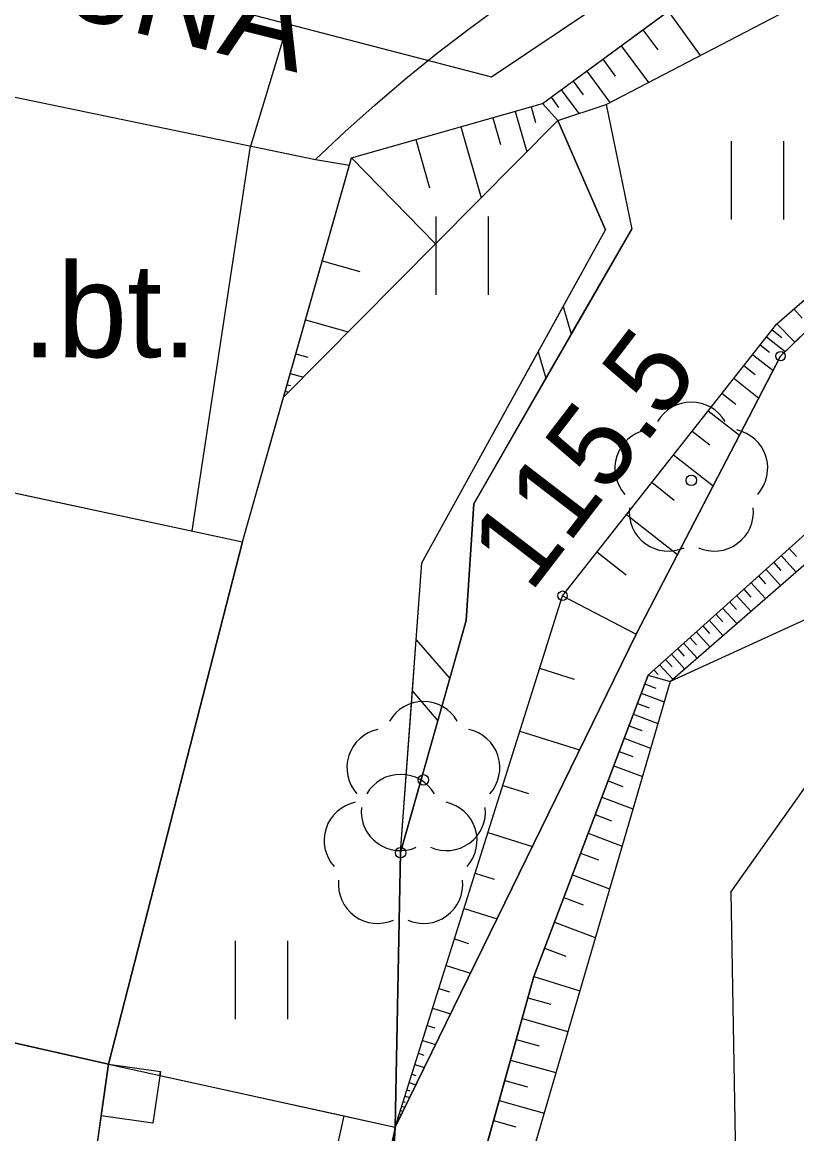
# Model space of a CAD drawing. Extents: x 6434771 to 6436222, y 5663454 to 5664782.
# Drawn here: x 6434919.55 to 6434926.97, y 5664029.23 to 5664039.87 of the extents above; entities that cross this region are included whole.
import ezdxf

# ---------------------------------------------------------------- set-up
doc = ezdxf.new("R2010")
doc.units = 0
for name, color, linetype in [('Warstwa 1', 7, 'Continuous'), ('Warstwa 10', 7, 'Continuous'), ('Warstwa 11', 7, 'Continuous'), ('Warstwa 12', 7, 'Continuous'), ('Warstwa 13', 7, 'Continuous'), ('Warstwa 2', 7, 'Continuous'), ('Warstwa 20', 7, 'Continuous'), ('Warstwa 21', 7, 'Continuous'), ('Warstwa 33', 7, 'Continuous'), ('Warstwa 5', 7, 'Continuous'), ('Warstwa 51', 7, 'Continuous'), ('Warstwa 8', 7, 'Continuous'), ('Warstwa 9', 7, 'Continuous')]:
    doc.layers.add(name, color=color, linetype=linetype)

msp = doc.modelspace()

# ---------------------------------------------------------------- linework, layer by layer
at = {"layer": 'Warstwa 1'}
for q in [(6434931.371, 5664038.648), (6434926.577, 5664017.347)]:
    msp.add_line((6434926.337, 5664031.543), q, dxfattribs=at)
for points in [[(6434917.94, 5664035.694), (6434921.661, 5664034.898), (6434920.38, 5664029.894), (6434916.633, 5664030.739)], [(6434911.812, 5664031.828), (6434920.38, 5664029.894), (6434918.982, 5664020.154), (6434921.832, 5664020.166), (6434921.856, 5664014.645), (6434919.005, 5664014.634), (6434920.397, 5664004.883), (6434911.753, 5664002.928), (6434910.828, 5664006.639), (6434910.117, 5664010.758), (6434909.494, 5664014.626), (6434909.488, 5664017.416), (6434909.44, 5664020.046), (6434910.163, 5664023.638), (6434910.979, 5664028.218)]]:
    msp.add_lwpolyline(points, close=True, dxfattribs=at)
at = {"layer": 'Warstwa 10'}
for p, q in [((6434925.142, 5664039.086), (6434929.479, 5664041.344)), ((6434924.532, 5664039.094), (6434926.338, 5664040.422)), ((6434925.735, 5664039.978), (6434926.044, 5664039.556)), ((6434925.494, 5664039.802), (6434925.636, 5664039.609)), ((6434925.288, 5664039.649), (6434925.547, 5664039.297)), ((6434925.11, 5664039.52), (6434925.23, 5664039.357)), ((6434924.958, 5664039.406), (6434925.179, 5664039.106)), ((6434924.826, 5664039.31), (6434924.924, 5664039.178)), ((6434924.712, 5664039.226), (6434924.88, 5664038.998)), ((6434922.705, 5664038.576), (6434924.532, 5664039.094)), ((6434924.532, 5664039.094), (6434924.68, 5664038.932)), ((6434924.68, 5664038.932), (6434924.532, 5664039.094)), ((6434924.615, 5664039.156), (6434924.688, 5664039.057)), ((6434924.68, 5664038.932), (6434925.142, 5664039.086)), ((6434924.273, 5664039.02), (6434924.383, 5664038.632)), ((6434924.424, 5664039.063), (6434924.467, 5664038.912)), ((6434923.515, 5664037.757), (6434924.68, 5664038.932)), ((6434923.753, 5664038.873), (6434923.946, 5664038.192)), ((6434924.058, 5664038.959), (6434924.13, 5664038.704)), ((6434923.321, 5664038.75), (6434923.453, 5664038.289)), ((6434922.054, 5664036.284), (6434922.705, 5664038.576)), ((6434922.705, 5664038.576), (6434923.509, 5664037.752)), ((6434925.546, 5664033.621), (6434930.763, 5664038.318)), ((6434925.755, 5664033.559), (6434930.9, 5664038.046)), ((6434922.054, 5664036.284), (6434923.515, 5664037.757)), ((6434922.425, 5664037.588), (6434922.785, 5664037.486)), ((6434922.264, 5664037.023), (6434922.673, 5664036.907)), ((6434922.171, 5664036.697), (6434922.286, 5664036.665)), ((6434922.119, 5664036.51), (6434922.244, 5664036.474)), ((6434922.07, 5664036.339), (6434922.101, 5664036.331)), ((6434922.088, 5664036.402), (6434922.121, 5664036.393)), ((6434922.061, 5664036.304), (6434922.066, 5664036.302)), ((6434926.893, 5664034.835), (6434926.965, 5664034.756)), ((6434926.819, 5664034.767), (6434926.96, 5664034.61)), ((6434926.672, 5664034.634), (6434926.811, 5664034.48)), ((6434926.745, 5664034.701), (6434926.815, 5664034.623)), ((6434926.529, 5664034.507), (6434926.668, 5664034.355)), ((6434926.6, 5664034.57), (6434926.669, 5664034.494)), ((6434926.46, 5664034.444), (6434926.528, 5664034.368)), ((6434926.325, 5664034.323), (6434926.392, 5664034.248)), ((6434926.392, 5664034.383), (6434926.527, 5664034.232)), ((6434926.194, 5664034.204), (6434926.26, 5664034.13)), ((6434926.258, 5664034.263), (6434926.393, 5664034.115)), ((6434926.067, 5664034.091), (6434926.132, 5664034.018)), ((6434926.13, 5664034.147), (6434926.261, 5664034)), ((6434925.945, 5664033.98), (6434926.009, 5664033.909)), ((6434926.006, 5664034.035), (6434926.135, 5664033.891)), ((6434925.826, 5664033.874), (6434925.89, 5664033.803)), ((6434925.884, 5664033.926), (6434926.013, 5664033.783)), ((6434925.711, 5664033.77), (6434925.775, 5664033.7)), ((6434925.768, 5664033.821), (6434925.894, 5664033.681)), ((6434925.6, 5664033.67), (6434925.641, 5664033.625)), ((6434925.655, 5664033.72), (6434925.78, 5664033.58)), ((6434925.546, 5664033.621), (6434925.755, 5664033.559)), ((6434925.546, 5664033.621), (6434925.755, 5664033.559))]:
    msp.add_line(p, q, dxfattribs=at)
at = {"layer": 'Warstwa 11'}
msp.add_lwpolyline([(6434966.756, 5664003.6), (6434966.415, 5664007.644), (6434965.276, 5664011.028), (6434962.407, 5664016.883), (6434961.412, 5664023.136), (6434959.23, 5664027.952), (6434956.702, 5664030.613), (6434952.189, 5664033.718), (6434942.648, 5664038.634), (6434938.947, 5664040.259), (6434935.85, 5664038.056), (6434933.246, 5664036.108), (6434929.415, 5664035.234), (6434925.755, 5664033.559), (6434924.242, 5664028.377), (6434923.988, 5664023.91), (6434923.741, 5664023.373), (6434924.496, 5664011.353), (6434925.122, 5664008.575), (6434925.857, 5664004.846)], dxfattribs=at)
for centre in [(6434925.958, 5664035.486), (6434923.393, 5664032.617), (6434923.175, 5664031.92)]:
    msp.add_circle(centre, 0.05, dxfattribs=at)
for centre, start, end in [((6434925.958, 5664035.861), 30.1471, 149.8529), ((6434925.601, 5664035.602), 102.1471, 221.8529), ((6434926.315, 5664035.602), 318.1471, 77.8529), ((6434925.738, 5664035.183), 174.1471, 293.8529), ((6434926.178, 5664035.183), 246.1471, 5.8529), ((6434923.393, 5664032.992), 30.1471, 149.8529), ((6434923.036, 5664032.733), 102.1471, 221.8529), ((6434923.75, 5664032.733), 318.1471, 77.8529), ((6434923.175, 5664032.295), 30.1471, 149.8529), ((6434922.818, 5664032.036), 102.1471, 221.8529), ((6434923.532, 5664032.036), 318.1471, 77.8529), ((6434923.173, 5664032.314), 174.1471, 293.8529), ((6434923.613, 5664032.314), 246.1471, 5.8529), ((6434922.955, 5664031.617), 174.1471, 293.8529), ((6434923.395, 5664031.617), 246.1471, 5.8529)]:
    msp.add_arc(centre, 0.375, start, end, dxfattribs=at)
at = {"layer": 'Warstwa 12'}
for points in [[(6434921.179, 5664035.001), (6434921.736, 5664038.668), (6434924.809, 5664048.81)], [(6434916.87, 5664040.657), (6434919.588, 5664040.514), (6434924.045, 5664039.35), (6434927.322, 5664041.55), (6434931.207, 5664042.783), (6434934.74, 5664042.98), (6434942.258, 5664041.148), (6434950.666, 5664036.716), (6434956.042, 5664033.861), (6434958.491, 5664032.141), (6434963.807, 5664027.637), (6434974.145, 5664019.101)]]:
    msp.add_lwpolyline(points, dxfattribs=at)
at = {"layer": 'Warstwa 13'}
for centre in [(6434926.813, 5664036.676), (6434924.725, 5664034.381)]:
    msp.add_circle(centre, 0.045, dxfattribs=at)
at = {"layer": 'Warstwa 2'}
msp.add_lwpolyline([(6434921.661, 5664034.898), (6434922.705, 5664038.576), (6434924.532, 5664039.094), (6434926.338, 5664040.422), (6434928.301, 5664041.518), (6434930.459, 5664042.152), (6434933.603, 5664042.424), (6434935.842, 5664042.316), (6434938.067, 5664041.859), (6434940.24, 5664041.293), (6434942.361, 5664040.517), (6434946.478, 5664038.627), (6434952.38, 5664035.426), (6434958.066, 5664031.766), (6434964.917, 5664026.013)], dxfattribs=at)
at = {"layer": 'Warstwa 20'}
for p, q in [((6434924.532, 5664039.094), (6434926.338, 5664040.422)), ((6434922.705, 5664038.576), (6434924.532, 5664039.094)), ((6434922.054, 5664036.284), (6434922.705, 5664038.576)), ((6434925.546, 5664033.621), (6434930.763, 5664038.318))]:
    msp.add_line(p, q, dxfattribs=at)
for points in [[(6434923.123, 5664029.29), (6434924.725, 5664034.381), (6434926.776, 5664036.986), (6434930.011, 5664039.797)], [(6434925.546, 5664033.621), (6434924.451, 5664030.734), (6434923.907, 5664028.791), (6434923.383, 5664023.537), (6434924.334, 5664011.185), (6434924.872, 5664008.518), (6434925.668, 5664004.869), (6434925.2, 5664002.574), (6434924.237, 5663999.066), (6434924.128, 5663997.437), (6434924.248, 5663995.845)], [(6434921.832, 5664020.166), (6434923.123, 5664029.29)]]:
    msp.add_lwpolyline(points, dxfattribs=at)
at = {"layer": 'Warstwa 21'}
for p, q in [((6434925.142, 5664039.086), (6434929.479, 5664041.344)), ((6434924.68, 5664038.932), (6434925.142, 5664039.086)), ((6434923.515, 5664037.757), (6434924.68, 5664038.932)), ((6434925.755, 5664033.559), (6434930.9, 5664038.046)), ((6434922.054, 5664036.284), (6434923.515, 5664037.757))]:
    msp.add_line(p, q, dxfattribs=at)
for points in [[(6434930.011, 5664039.797), (6434926.813, 5664036.676), (6434925.43, 5664034.013), (6434923.123, 5664029.29)], [(6434925.755, 5664033.559), (6434924.242, 5664028.377), (6434923.988, 5664023.91), (6434923.741, 5664023.373), (6434924.496, 5664011.353), (6434925.122, 5664008.575), (6434925.857, 5664004.846), (6434925.409, 5664002.512), (6434924.476, 5663998.973), (6434924.338, 5663997.464), (6434924.499, 5663995.882)], [(6434923.123, 5664029.29), (6434922.795, 5664023.654), (6434921.832, 5664020.166)]]:
    msp.add_lwpolyline(points, dxfattribs=at)
at = {"layer": 'Warstwa 33'}
for p, q in [((6434918.982, 5664020.154), (6434920.38, 5664029.894)), ((6434920.38, 5664029.894), (6434923.123, 5664029.29)), ((6434921.832, 5664020.166), (6434923.123, 5664029.29))]:
    msp.add_line(p, q, dxfattribs=at)
for points in [[(6434920.875, 5664029.823), (6434920.804, 5664029.328), (6434920.309, 5664029.399), (6434920.38, 5664029.894)], [(6434923.015, 5664028.802), (6434922.527, 5664028.91), (6434922.635, 5664029.398), (6434923.123, 5664029.29)]]:
    msp.add_lwpolyline(points, close=True, dxfattribs=at)
at = {"layer": 'Warstwa 5'}
for p, q in [((6434925.142, 5664039.086), (6434929.479, 5664041.344)), ((6434924.532, 5664039.094), (6434926.338, 5664040.422)), ((6434923.834, 5664039.815), (6434924.147, 5664040.044)), ((6434923.527, 5664039.579), (6434923.834, 5664039.815)), ((6434926.776, 5664036.986), (6434930.011, 5664039.797)), ((6434926.813, 5664036.676), (6434930.011, 5664039.797)), ((6434923.226, 5664039.335), (6434923.527, 5664039.579)), ((6434922.931, 5664039.083), (6434923.226, 5664039.335)), ((6434922.642, 5664038.825), (6434922.931, 5664039.083)), ((6434922.705, 5664038.576), (6434924.532, 5664039.094)), ((6434925.142, 5664039.086), (6434925.387, 5664037.893)), ((6434923.515, 5664037.757), (6434924.68, 5664038.932)), ((6434924.68, 5664038.932), (6434925.137, 5664037.886)), ((6434922.359, 5664038.559), (6434922.642, 5664038.825)), ((6434926.344, 5664037.984), (6434926.344, 5664038.734)), ((6434926.844, 5664037.984), (6434926.844, 5664038.734)), ((6434922.359, 5664038.559), (6434922.685, 5664038.505)), ((6434922.685, 5664038.505), (6434922.705, 5664038.576)), ((6434925.546, 5664033.621), (6434930.763, 5664038.318)), ((6434923.515, 5664037.262), (6434923.515, 5664038.012)), ((6434924.015, 5664037.262), (6434924.015, 5664038.012)), ((6434924.732, 5664037.152), (6434925.137, 5664037.886)), ((6434924.809, 5664036.886), (6434925.387, 5664037.893)), ((6434922.054, 5664036.284), (6434923.515, 5664037.757)), ((6434924.493, 5664036.718), (6434924.732, 5664037.152)), ((6434924.725, 5664034.381), (6434926.776, 5664036.986)), ((6434924.566, 5664036.464), (6434924.809, 5664036.886)), ((6434923.378, 5664034.697), (6434924.493, 5664036.718)), ((6434925.43, 5664034.013), (6434926.813, 5664036.676)), ((6434923.875, 5664035.261), (6434924.566, 5664036.464)), ((6434921.661, 5664034.898), (6434922.054, 5664036.284)), ((6434923.802, 5664034.142), (6434923.875, 5664035.261)), ((6434920.38, 5664029.894), (6434921.661, 5664034.898)), ((6434923.324, 5664033.959), (6434923.378, 5664034.697)), ((6434923.123, 5664029.29), (6434924.725, 5664034.381)), ((6434923.645, 5664033.587), (6434923.802, 5664034.142)), ((6434923.123, 5664029.29), (6434925.43, 5664034.013)), ((6434923.288, 5664033.466), (6434923.324, 5664033.959)), ((6434923.532, 5664033.184), (6434923.645, 5664033.587)), ((6434924.451, 5664030.734), (6434925.546, 5664033.621)), ((6434923.175, 5664031.92), (6434923.288, 5664033.466)), ((6434923.175, 5664031.92), (6434923.532, 5664033.184)), ((6434923.123, 5664029.29), (6434923.175, 5664031.92)), ((6434923.123, 5664029.29), (6434923.175, 5664031.92)), ((6434921.594, 5664030.324), (6434921.594, 5664031.074)), ((6434922.094, 5664030.324), (6434922.094, 5664031.074)), ((6434923.907, 5664028.791), (6434924.451, 5664030.734)), ((6434920.38, 5664029.894), (6434920.875, 5664029.823)), ((6434920.87, 5664029.786), (6434920.875, 5664029.823)), ((6434920.87, 5664029.786), (6434922.635, 5664029.398)), ((6434922.635, 5664029.398), (6434923.123, 5664029.29)), ((6434922.795, 5664023.654), (6434923.123, 5664029.29))]:
    msp.add_line(p, q, dxfattribs=at)
at = {"layer": 'Warstwa 51'}
for p, q in [((6434924.732, 5664037.152), (6434924.809, 5664036.886)), ((6434924.493, 5664036.718), (6434924.566, 5664036.464)), ((6434923.324, 5664033.959), (6434923.645, 5664033.587)), ((6434923.288, 5664033.466), (6434923.531, 5664033.184))]:
    msp.add_line(p, q, dxfattribs=at)
msp.add_lwpolyline([(6434923.123, 5664029.29), (6434923.175, 5664031.92), (6434923.378, 5664034.697), (6434925.137, 5664037.886), (6434924.68, 5664038.932), (6434925.142, 5664039.086), (6434925.387, 5664037.893), (6434923.875, 5664035.261), (6434923.802, 5664034.142), (6434923.175, 5664031.92), (6434923.123, 5664029.29)], dxfattribs=at)
at = {"layer": 'Warstwa 8'}
for p, q in [((6434918.911, 5664039.273), (6434922.359, 5664038.559)), ((6434922.359, 5664038.559), (6434922.685, 5664038.505)), ((6434921.661, 5664034.898), (6434922.685, 5664038.505)), ((6434917.94, 5664035.694), (6434921.661, 5664034.898))]:
    msp.add_line(p, q, dxfattribs=at)
at = {"layer": 'Warstwa 9'}
for p, q in [((6434923.834, 5664039.815), (6434924.147, 5664040.044)), ((6434923.527, 5664039.579), (6434923.834, 5664039.815)), ((6434923.226, 5664039.335), (6434923.527, 5664039.579)), ((6434922.931, 5664039.083), (6434923.226, 5664039.335)), ((6434918.911, 5664039.273), (6434922.359, 5664038.559)), ((6434922.642, 5664038.825), (6434922.931, 5664039.083)), ((6434922.359, 5664038.559), (6434922.642, 5664038.825)), ((6434926.941, 5664037.129), (6434927.018, 5664037.04)), ((6434926.776, 5664036.986), (6434926.949, 5664036.809)), ((6434926.678, 5664036.86), (6434926.857, 5664036.719)), ((6434926.731, 5664036.928), (6434926.825, 5664036.854)), ((6434926.616, 5664036.783), (6434926.706, 5664036.712)), ((6434926.545, 5664036.692), (6434926.741, 5664036.538)), ((6434926.462, 5664036.586), (6434926.57, 5664036.501)), ((6434926.364, 5664036.463), (6434926.604, 5664036.274)), ((6434926.251, 5664036.32), (6434926.385, 5664036.214)), ((6434926.119, 5664036.152), (6434926.418, 5664035.917)), ((6434925.966, 5664035.957), (6434926.134, 5664035.825)), ((6434925.787, 5664035.73), (6434926.167, 5664035.432)), ((6434925.579, 5664035.467), (6434925.794, 5664035.297)), ((6434925.337, 5664035.159), (6434925.826, 5664034.774)), ((6434925.055, 5664034.8), (6434925.333, 5664034.581)), ((6434924.725, 5664034.381), (6434925.43, 5664034.013)), ((6434924.506, 5664033.686), (6434924.837, 5664033.582)), ((6434925.479, 5664033.447), (6434925.698, 5664033.364)), ((6434925.514, 5664033.537), (6434925.619, 5664033.496)), ((6434925.442, 5664033.349), (6434925.556, 5664033.307)), ((6434925.403, 5664033.246), (6434925.638, 5664033.157)), ((6434925.362, 5664033.135), (6434925.483, 5664033.089)), ((6434924.317, 5664033.085), (6434924.889, 5664032.905)), ((6434925.316, 5664033.016), (6434925.568, 5664032.92)), ((6434925.268, 5664032.889), (6434925.399, 5664032.84)), ((6434925.216, 5664032.753), (6434925.49, 5664032.65)), ((6434925.161, 5664032.608), (6434925.304, 5664032.554)), ((6434924.153, 5664032.564), (6434924.4, 5664032.486)), ((6434925.101, 5664032.452), (6434925.399, 5664032.339)), ((6434925.038, 5664032.284), (6434925.194, 5664032.225)), ((6434924.011, 5664032.114), (6434924.437, 5664031.98)), ((6434924.971, 5664032.106), (6434925.295, 5664031.983)), ((6434924.898, 5664031.914), (6434925.068, 5664031.85)), ((6434923.888, 5664031.723), (6434924.072, 5664031.666)), ((6434924.82, 5664031.709), (6434925.176, 5664031.575)), ((6434924.737, 5664031.49), (6434924.924, 5664031.42)), ((6434923.782, 5664031.385), (6434924.098, 5664031.286)), ((6434924.648, 5664031.255), (6434925.039, 5664031.106)), ((6434923.69, 5664031.093), (6434923.826, 5664031.05)), ((6434924.553, 5664031.004), (6434924.758, 5664030.927)), ((6434923.61, 5664030.839), (6434923.844, 5664030.765)), ((6434924.451, 5664030.734), (6434924.89, 5664030.597)), ((6434923.541, 5664030.619), (6434923.642, 5664030.588)), ((6434924.394, 5664030.531), (6434924.614, 5664030.469)), ((6434923.481, 5664030.429), (6434923.653, 5664030.375)), ((6434923.43, 5664030.264), (6434923.502, 5664030.241)), ((6434924.338, 5664030.331), (6434924.776, 5664030.208)), ((6434923.384, 5664030.121), (6434923.51, 5664030.082)), ((6434924.282, 5664030.131), (6434924.5, 5664030.071)), ((6434923.345, 5664029.998), (6434923.398, 5664029.981)), ((6434924.227, 5664029.934), (6434924.661, 5664029.813)), ((6434923.312, 5664029.89), (6434923.402, 5664029.862)), ((6434923.257, 5664029.718), (6434923.322, 5664029.697)), ((6434923.283, 5664029.798), (6434923.321, 5664029.786)), ((6434924.172, 5664029.739), (6434924.389, 5664029.678)), ((6434923.235, 5664029.648), (6434923.262, 5664029.64)), ((6434923.2, 5664029.536), (6434923.219, 5664029.529)), ((6434923.217, 5664029.587), (6434923.261, 5664029.574)), ((6434924.118, 5664029.546), (6434924.549, 5664029.426)), ((6434923.153, 5664029.388), (6434923.161, 5664029.386)), ((6434923.162, 5664029.417), (6434923.181, 5664029.411)), ((6434923.174, 5664029.451), (6434923.186, 5664029.448)), ((6434923.185, 5664029.491), (6434923.216, 5664029.481)), ((6434923.123, 5664029.29), (6434923.123, 5664029.29)), ((6434923.123, 5664029.29), (6434923.123, 5664029.29)), ((6434923.127, 5664029.304), (6434923.128, 5664029.304)), ((6434923.132, 5664029.321), (6434923.137, 5664029.32)), ((6434923.139, 5664029.34), (6434923.143, 5664029.339)), ((6434923.146, 5664029.362), (6434923.157, 5664029.359)), ((6434924.065, 5664029.355), (6434924.279, 5664029.295))]:
    msp.add_line(p, q, dxfattribs=at)
for points in [[(6434923.123, 5664029.29), (6434924.725, 5664034.381), (6434926.776, 5664036.986), (6434930.011, 5664039.797), (6434926.813, 5664036.676), (6434925.43, 5664034.013)], [(6434924.248, 5663995.845), (6434924.128, 5663997.437), (6434924.237, 5663999.066), (6434925.2, 5664002.574), (6434925.668, 5664004.869), (6434924.872, 5664008.518), (6434924.334, 5664011.185), (6434923.383, 5664023.537), (6434923.907, 5664028.791), (6434924.451, 5664030.734), (6434925.546, 5664033.621), (6434925.755, 5664033.559), (6434924.242, 5664028.377), (6434923.988, 5664023.91), (6434923.741, 5664023.373), (6434924.496, 5664011.353), (6434925.122, 5664008.575), (6434925.857, 5664004.846), (6434925.409, 5664002.512), (6434924.476, 5663998.973), (6434924.338, 5663997.464), (6434924.499, 5663995.882)], [(6434921.832, 5664020.166), (6434923.123, 5664029.29), (6434922.795, 5664023.654)]]:
    msp.add_lwpolyline(points, close=True, dxfattribs=at)

# ---------------------------------------------------------------- texts
at = {"layer": 'Warstwa 13'}
for s, height, rotation, p in [('2eNA', 0.9, 346.055, (6434919.265, 5664040.115)), ('115.5', 0.8, 52.4715, (6434924.417, 5664034.396))]:
    msp.add_text(s, height=height, rotation=rotation, dxfattribs=at).set_placement(p)
at = {"layer": 'Warstwa 8'}
msp.add_text('j.bt.', height=0.9, dxfattribs=at).set_placement((6434919.286, 5664036.665))

doc.saveas('drawing.dxf')
